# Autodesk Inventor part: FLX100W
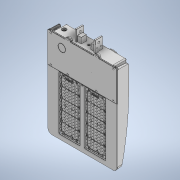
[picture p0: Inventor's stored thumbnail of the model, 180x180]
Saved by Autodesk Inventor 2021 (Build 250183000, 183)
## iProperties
Created: 2020-07
Part Number: FLX100W
Material: Generic
Description: STEP AP203
Document SubType Name: Modeling
Designer: DarrinWoodcock
Density: 1 g/cm^3
Appearance: Default
Title: FLK100W.STEP
Author: admin
Sending System: SolidWorks 2016
Preprocessor: SwSTEP 2.0
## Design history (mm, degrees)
feature "FLK100W-20170727_1:1"
feature "FLK-PCB-90-6-15-0710_2:1"
feature "HVG-100-42B_3:1"
feature "Ç°¸Ç£¨FLKI100W£©20170822ÐÞ¸Ä_10:1"
feature "FLK150WÇ°¸Ç·ÀË®È¦´òÑùÍ¼-0815_11:1"
feature "170714-JYTL-FLK100W-90ºÏ1Í¸¾µ£¨ÎÞ¹âÑ§£©_5:1"
feature "170714-JYTL-FLK100W-90ºÏ1Í¸¾µ£¨ÎÞ¹âÑ§£©_6:1"
feature "°²×°Åä¼þ_7:1"
feature "FLK-PCB-90-6-15-0710_8:1"
feature "°²×°Åä¼þ_9:1"
body "Solid1"
body "Solid2"
body "Solid3"
body "Solid4"
body "Solid5"
body "Solid6"
body "Solid7"
body "Solid8"
body "Solid9"
body "Solid10"
